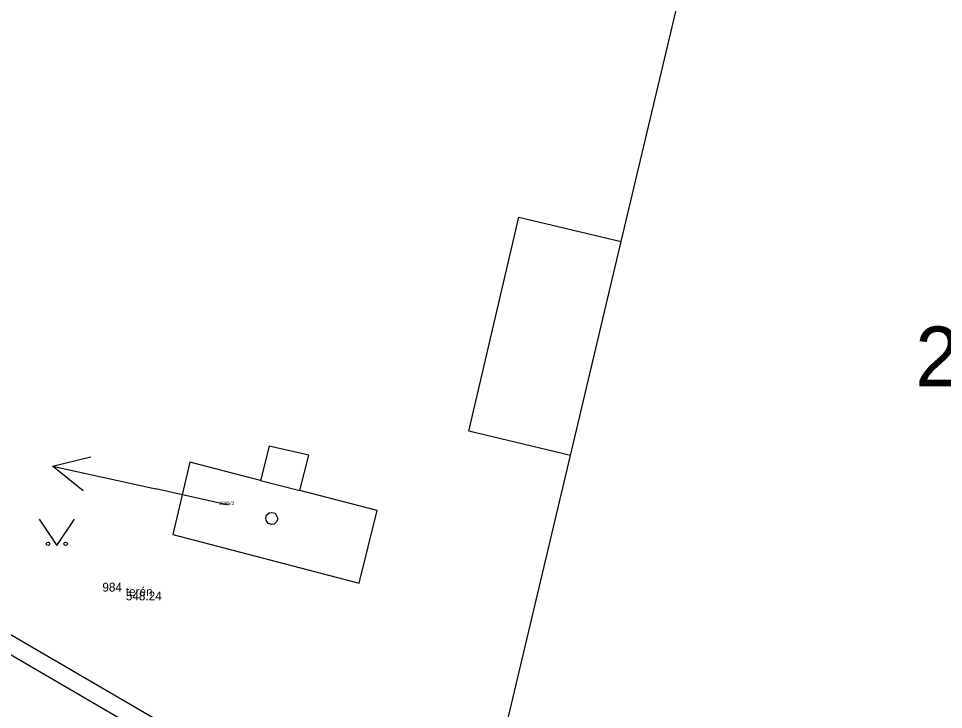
# Model space of a CAD drawing. Extents: x -528274 to -527531, y -1079304 to -1078580.
# Drawn here: x -527787.93 to -527761.62, y -1079083.6 to -1079063.93 of the extents above; entities that cross this region are included whole.
import ezdxf

# ---------------------------------------------------------------- set-up
doc = ezdxf.new("R2010")
doc.units = 0
for name, color, linetype in [('BOD_CISLO', 7, 'Continuous'), ('BOD_KOD', 7, 'Continuous'), ('BOD_VYSKA', 7, 'Continuous'), ('BOD_ZNACKA', 7, 'Continuous'), ('g_vegetace', 7, 'Continuous'), ('g_zeď', 7, 'Continuous'), ('katastrální mapa', 7, 'Continuous'), ('Level 1', 7, 'Continuous'), ('Level 26', 7, 'Continuous')]:
    doc.layers.add(name, color=color, linetype=linetype)

# ---------------------------------------------------------------- blocks, each defined once
blk = doc.blocks.new('3.140')
at = {"layer": 'BOD_CISLO'}
blk.add_lwpolyline([(-0.1, 0.15), (0, 0), (0.1, 0.15)], dxfattribs=at)
for centre in [(-0.05, 0.01), (0.05, 0.01)]:
    blk.add_circle(centre, 0.01, dxfattribs=at)

msp = doc.modelspace()

# ---------------------------------------------------------------- linework, layer by layer
at = {"layer": 'BOD_ZNACKA'}
msp.add_line((-527784.88, -1079080.24), (-527784.88, -1079080.24), dxfattribs=at)
at = {"layer": 'g_zeď'}
msp.add_lwpolyline([(-527781.312, -1079088.363), (-527780.344, -1079086.021), (-527799.111, -1079075.089), (-527814.21, -1079066.424), (-527817.935, -1079067.734), (-527817.711, -1079068.313), (-527814.168, -1079067.032), (-527799.323, -1079075.526), (-527780.924, -1079086.249), (-527781.76, -1079088.168)], dxfattribs=at)
at = {"layer": 'katastrální mapa'}
for p, q in [((-527770.79, -1079070.28), (-527767.37, -1079055.89)), ((-527775.12, -1079075.68), (-527773.7, -1079069.59)), ((-527773.7, -1079069.59), (-527770.79, -1079070.28)), ((-527772.23, -1079076.37), (-527770.79, -1079070.28)), ((-527772.23, -1079076.37), (-527775.12, -1079075.68)), ((-527780.8, -1079076.1), (-527781.05, -1079077.08)), ((-527779.67, -1079076.36), (-527780.8, -1079076.1)), ((-527779.93, -1079077.36), (-527779.67, -1079076.36)), ((-527775.14, -1079088.62), (-527772.23, -1079076.37)), ((-527786.96, -1079076.675), (-527784.03, -1079077.32)), ((-527783.06, -1079076.56), (-527783.54, -1079078.62)), ((-527781.05, -1079077.08), (-527783.06, -1079076.56)), ((-527781.05, -1079077.08), (-527779.93, -1079077.36)), ((-527781.96, -1079077.78), (-527784.03, -1079077.32)), ((-527777.73, -1079077.93), (-527779.93, -1079077.36)), ((-527778.24, -1079080), (-527777.73, -1079077.93)), ((-527783.54, -1079078.62), (-527778.24, -1079080))]:
    msp.add_line(p, q, dxfattribs=at)
msp.add_lwpolyline([(-527786.091, -1079077.378), (-527786.96, -1079076.675), (-527785.876, -1079076.402)], dxfattribs=at)
msp.add_lwpolyline([(-527780.73, -1079077.99), (-527780.63, -1079078.01), (-527780.58, -1079078.1), (-527780.56, -1079078.16), (-527780.58, -1079078.25), (-527780.66, -1079078.32), (-527780.73, -1079078.33), (-527780.82, -1079078.3), (-527780.88, -1079078.24), (-527780.9, -1079078.16), (-527780.88, -1079078.07), (-527780.8, -1079078)], close=True, dxfattribs=at)
at = {"layer": 'Level 1'}
msp.add_line((-527784.876, -1079080.241), (-527784.876, -1079080.241), dxfattribs=at)
at = {"layer": 'Level 26'}
msp.add_line((-527784.88, -1079080.24), (-527784.88, -1079080.24), dxfattribs=at)

# ---------------------------------------------------------------- block references
at = {"layer": 'g_vegetace', "xscale": 5, "yscale": 5}
msp.add_blockref('3.140', (-527786.841, -1079078.933), dxfattribs=at)

# ---------------------------------------------------------------- texts
at = {"layer": 'BOD_CISLO'}
msp.add_text('984', height=0.25, dxfattribs=at).set_placement((-527785.547, -1079080.24))
at = {"layer": 'BOD_KOD'}
msp.add_text('terén', height=0.25, dxfattribs=at).set_placement((-527784.88, -1079080.365))
at = {"layer": 'BOD_VYSKA'}
msp.add_text('548.24', height=0.25, dxfattribs=at).set_placement((-527784.88, -1079080.49))
at = {"layer": 'katastrální mapa'}
for s, height, p in [('2307', 1.7, (-527762.423, -1079074.4)), ('2295/2', 0.1, (-527782.218, -1079077.78))]:
    msp.add_text(s, height=height, dxfattribs=at).set_placement(p)

doc.saveas('drawing.dxf')
